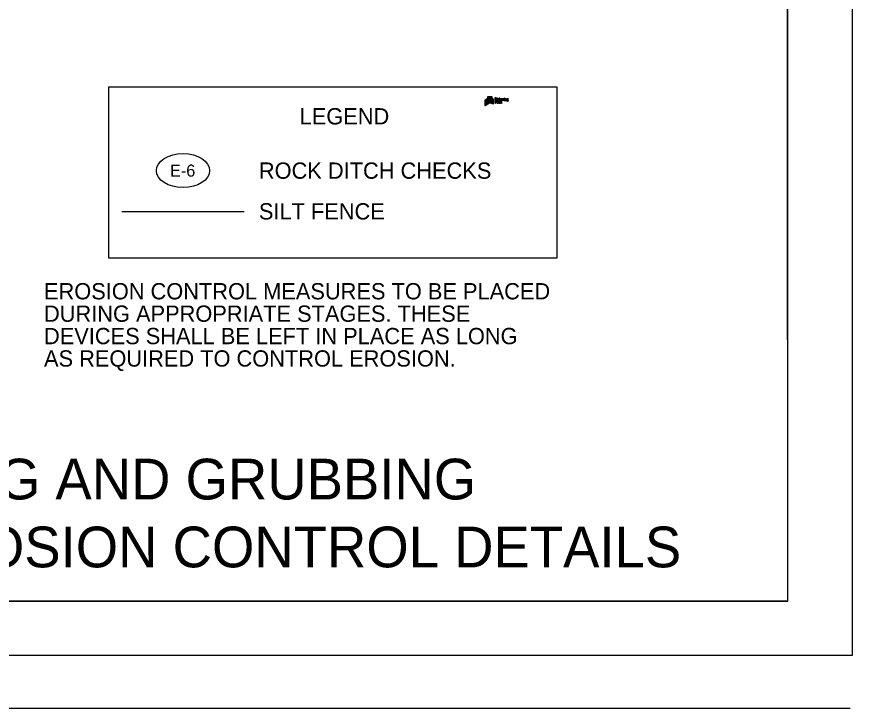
# Model space of a CAD drawing. Extents: x 7675 to 14104, y 9961 to 11168.
# Drawn here: x 9527.7 to 9835.3, y 9960.6 to 10215.3 of the extents above; entities that cross this region are included whole.
import ezdxf

# ---------------------------------------------------------------- set-up
doc = ezdxf.new("R2010")
doc.units = 0
for name, color, linetype in [('GREEN_TXT', 7, 'Continuous'), ('Legend', 7, 'Continuous'), ('SEAL-INFO', 7, 'Continuous'), ('Stage 1 Ditch Checks', 7, 'Continuous'), ('Stage 2 Flow Arrows', 7, 'Continuous')]:
    doc.layers.add(name, color=color, linetype=linetype)

msp = doc.modelspace()

# ---------------------------------------------------------------- linework, layer by layer
at = {"layer": 'GREEN_TXT'}
for p, q in [((9811.58, 10000), (9811.58, 11027.3)), ((9811.58, 10000), (8230.68, 10000)), ((8074.58, 9960.6), (9834.58, 9960.6))]:
    msp.add_line(p, q, dxfattribs=at)
at = {"layer": 'Legend'}
for p, q in [((9700.15, 10183.63), (9701.35, 10184.33)), ((9700.15, 10183.1), (9701.56, 10183.92)), ((9700.15, 10182.58), (9701.76, 10183.5)), ((9701.43, 10185.41), (9702.36, 10185.41)), ((9702.39, 10185.39), (9702.48, 10184.8)), ((9703.7, 10184.29), (9703.7, 10184.3)), ((9703.7, 10183.49), (9703.7, 10183.49)), ((9703.71, 10185.3), (9703.71, 10185.3)), ((9703.71, 10184.49), (9703.71, 10184.49)), ((9703.72, 10183.51), (9703.72, 10183.51)), ((9703.72, 10183.46), (9703.91, 10183.46)), ((9703.73, 10184.51), (9703.73, 10184.51)), ((9703.73, 10184.25), (9703.73, 10183.53)), ((9703.74, 10184.47), (9703.92, 10184.47)), ((9703.75, 10185.26), (9703.75, 10184.54)), ((9703.9, 10183.97), (9703.9, 10184.19)), ((9703.9, 10183.53), (9703.9, 10183.85)), ((9703.91, 10184.92), (9703.91, 10185.21)), ((9703.91, 10184.54), (9703.91, 10184.77)), ((9703.91, 10183.5), (9703.91, 10183.51)), ((9703.92, 10184.8), (9704.17, 10184.87)), ((9703.92, 10184.21), (9704.32, 10184.21)), ((9704.2, 10183.95), (9703.92, 10183.95)), ((9703.92, 10183.87), (9704.2, 10183.87)), ((9703.93, 10185.24), (9704.02, 10185.24)), ((9703.93, 10184.51), (9703.93, 10184.51)), ((9703.93, 10183.49), (9703.93, 10183.49)), ((9704.06, 10184.96), (9703.94, 10184.9)), ((9703.94, 10184.49), (9703.94, 10184.49)), ((9704.23, 10183.84), (9704.23, 10183.83)), ((9704.35, 10184.18), (9704.35, 10184.16)), ((9704.47, 10184.49), (9704.47, 10184.49)), ((9704.48, 10183.47), (9704.69, 10183.47)), ((9704.49, 10184.47), (9704.71, 10184.47)), ((9704.49, 10184.01), (9704.49, 10184.01)), ((9704.5, 10185.02), (9704.5, 10185.01)), ((9704.64, 10184.05), (9704.5, 10184.05)), ((9704.66, 10185.06), (9704.51, 10185.06)), ((9704.51, 10183.99), (9704.51, 10183.53)), ((9704.52, 10184.99), (9704.52, 10184.54)), ((9704.67, 10183.54), (9704.67, 10184.03)), ((9704.68, 10184.54), (9704.68, 10185.04)), ((9704.69, 10183.51), (9704.69, 10183.51)), ((9704.71, 10184.51), (9704.7, 10184.52)), ((9704.86, 10183.46), (9705.07, 10183.46)), ((9704.87, 10184.01), (9704.87, 10184.01)), ((9705.03, 10184.05), (9704.88, 10184.05)), ((9704.89, 10183.99), (9704.89, 10183.53)), ((9705.05, 10183.53), (9705.05, 10183.86)), ((9705.07, 10183.51), (9705.07, 10183.51)), ((9705.25, 10184.9), (9705.32, 10184.98)), ((9705.39, 10184.47), (9705.6, 10184.47)), ((9705.39, 10184.01), (9705.39, 10184.01)), ((9705.4, 10185.28), (9705.4, 10185.28)), ((9705.55, 10185.32), (9705.41, 10185.32)), ((9705.41, 10183.99), (9705.41, 10183.53)), ((9705.42, 10185.26), (9705.42, 10184.53)), ((9705.57, 10184.86), (9705.57, 10185.3)), ((9705.57, 10184.53), (9705.57, 10184.67)), ((9705.57, 10183.54), (9705.57, 10183.86)), ((9705.58, 10184.69), (9705.65, 10184.75)), ((9705.6, 10183.51), (9705.59, 10183.51)), ((9705.76, 10184.97), (9705.61, 10184.84)), ((9705.68, 10184.74), (9705.81, 10184.53)), ((9705.75, 10185.04), (9705.77, 10185)), ((9705.77, 10183.51), (9705.77, 10183.51)), ((9705.98, 10185.07), (9705.78, 10185.07)), ((9705.79, 10184.47), (9706.05, 10184.47)), ((9705.8, 10183.86), (9705.8, 10183.54)), ((9706.02, 10184.52), (9705.81, 10184.87)), ((9705.82, 10184.9), (9705.97, 10185.03)), ((9705.96, 10183.54), (9705.96, 10183.87)), ((9705.98, 10185.03), (9705.99, 10185.03)), ((9705.98, 10183.51), (9705.98, 10183.51)), ((9706, 10185.04), (9706, 10185.05)), ((9706.18, 10184.9), (9706.18, 10184.9)), ((9706.18, 10183.87), (9706.18, 10183.53)), ((9706.19, 10184.82), (9706.54, 10184.82)), ((9706.4, 10184.87), (9706.21, 10184.87)), ((9706.34, 10183.54), (9706.34, 10183.87)), ((9706.37, 10183.51), (9706.37, 10183.51)), ((9706.55, 10184.62), (9706.55, 10184.62)), ((9706.65, 10184.47), (9706.86, 10184.47)), ((9706.81, 10185.06), (9706.66, 10185.06)), ((9706.66, 10185.02), (9706.66, 10185.01)), ((9706.67, 10184.99), (9706.67, 10184.54)), ((9706.84, 10184.54), (9706.84, 10184.87)), ((9706.86, 10184.51), (9706.86, 10184.52)), ((9707.12, 10184.47), (9707.33, 10184.47)), ((9707.28, 10185.06), (9707.13, 10185.06)), ((9707.13, 10185.02), (9707.13, 10185.01)), ((9707.14, 10184.99), (9707.14, 10184.54)), ((9707.3, 10184.54), (9707.3, 10185.03)), ((9707.33, 10184.51), (9707.33, 10184.52)), ((9707.44, 10185.02), (9707.45, 10185.01)), ((9707.44, 10184.47), (9707.65, 10184.47)), ((9707.6, 10185.06), (9707.45, 10185.06)), ((9707.46, 10184.99), (9707.46, 10184.54)), ((9707.62, 10184.54), (9707.62, 10184.87)), ((9707.65, 10184.51), (9707.65, 10184.52)), ((9707.82, 10184.47), (9708.03, 10184.47)), ((9707.85, 10184.87), (9707.85, 10184.54)), ((9708.01, 10184.54), (9708.01, 10184.87)), ((9708.03, 10184.51), (9708.03, 10184.52)), ((9708.71, 10185.06), (9708.47, 10185.06)), ((9708.54, 10184.94), (9708.54, 10184.65)), ((9708.56, 10184.46), (9708.56, 10184.46)), ((9708.67, 10184.63), (9708.67, 10184.98)), ((9708.68, 10185), (9708.72, 10185.02)), ((9566.44, 10143.59), (9611.44, 10143.59))]:
    msp.add_line(p, q, dxfattribs=at)
msp.add_lwpolyline([(9561.57, 10189.39), (9726.57, 10189.39), (9726.57, 10126.39), (9561.57, 10126.39)], close=True, dxfattribs=at)
for points in [[(9702.82, 10185.07), (9702.7, 10185.76), (9702.67, 10185.78), (9701.11, 10185.78), (9701.08, 10185.76), (9700.96, 10185.05), (9700.12, 10184.57), (9700.11, 10184.54), (9700.11, 10184.17), (9700.14, 10184.15)], [(9701.19, 10184.66), (9700.12, 10184.04), (9700.11, 10184.02), (9700.11, 10183.65), (9700.15, 10183.63)], [(9701.39, 10184.26), (9700.12, 10183.52), (9700.11, 10183.5), (9700.11, 10183.12), (9700.15, 10183.1)], [(9701.59, 10183.86), (9700.13, 10182.99), (9700.11, 10182.97), (9700.11, 10182.6), (9700.15, 10182.58)], [(9700.14, 10184.15), (9701.28, 10184.78), (9701.3, 10184.8), (9701.41, 10185.39)], [(9703.2, 10184.59), (9703.23, 10184.61), (9703.23, 10184.93), (9703.2, 10184.96)], [(9703.2, 10184.14), (9703.23, 10184.17), (9703.23, 10184.49), (9703.2, 10184.51)], [(9703.2, 10183.69), (9703.23, 10183.71), (9703.23, 10184.04), (9703.2, 10184.06)], [(9703.2, 10183.23), (9703.23, 10183.25), (9703.23, 10183.59), (9703.2, 10183.62)], [(9704.36, 10184.32), (9703.72, 10184.32), (9703.72, 10184.32)], [(9704.11, 10185.33), (9703.74, 10185.33), (9703.74, 10185.32)], [(9704.25, 10184.01), (9704.25, 10184.01), (9704.25, 10184.01), (9704.24, 10184), (9704.23, 10183.98)], [(9704.25, 10183.82), (9704.25, 10183.82), (9704.25, 10183.82)], [(9704.26, 10183.83), (9704.27, 10183.83), (9704.27, 10184), (9704.26, 10184)], [(9704.38, 10184.16), (9704.38, 10184.16), (9704.38, 10184.3)], [(9704.46, 10183.49), (9704.46, 10183.49), (9704.46, 10183.49)], [(9704.48, 10184.03), (9704.48, 10184.03), (9704.48, 10184.03)], [(9704.49, 10183.51), (9704.48, 10183.51), (9704.48, 10183.51)], [(9704.49, 10185.04), (9704.49, 10185.04), (9704.49, 10185.04)], [(9704.5, 10184.52), (9704.5, 10184.52), (9704.49, 10184.51)], [(9704.71, 10183.49), (9704.71, 10183.49), (9704.71, 10183.49)], [(9704.73, 10184.49), (9704.73, 10184.49), (9704.73, 10184.49)], [(9704.84, 10183.49), (9704.84, 10183.49), (9704.84, 10183.49)], [(9704.86, 10184.03), (9704.86, 10184.03), (9704.86, 10184.03)], [(9704.87, 10183.51), (9704.86, 10183.51), (9704.86, 10183.51)], [(9705.1, 10183.49), (9705.1, 10183.49), (9705.1, 10183.49)], [(9705.23, 10183.98), (9705.27, 10183.95), (9705.28, 10183.96), (9705.28, 10184.08), (9705.27, 10184.1), (9705.21, 10184.1)], [(9705.26, 10184.48), (9705.29, 10184.47), (9705.31, 10184.48), (9705.31, 10184.61)], [(9705.36, 10183.49), (9705.38, 10183.47), (9705.6, 10183.47), (9705.62, 10183.49)], [(9705.57, 10184.04), (9705.55, 10184.05), (9705.4, 10184.05), (9705.38, 10184.03)], [(9705.39, 10183.51), (9705.39, 10183.51), (9705.38, 10183.51)], [(9705.4, 10184.52), (9705.39, 10184.52), (9705.39, 10184.51)], [(9705.6, 10184.51), (9705.59, 10184.52), (9705.59, 10184.52)], [(9705.75, 10183.49), (9705.77, 10183.47), (9705.98, 10183.47), (9706, 10183.49)], [(9705.8, 10184.52), (9705.8, 10184.52), (9705.79, 10184.51)], [(9706.05, 10184.51), (9706.05, 10184.52), (9706.04, 10184.52)], [(9706.14, 10183.49), (9706.16, 10183.47), (9706.37, 10183.47), (9706.39, 10183.49)], [(9706.16, 10183.51), (9706.16, 10183.51), (9706.16, 10183.51)], [(9706.52, 10184.48), (9706.55, 10184.47), (9706.57, 10184.48), (9706.57, 10184.61)], [(9706.63, 10184.49), (9706.63, 10184.49), (9706.63, 10184.49)], [(9706.64, 10185.04), (9706.64, 10185.03), (9706.64, 10185.04)], [(9706.65, 10184.52), (9706.65, 10184.52), (9706.65, 10184.51)], [(9706.88, 10184.49), (9706.88, 10184.49), (9706.88, 10184.49)], [(9707.01, 10184.99), (9707.05, 10184.95), (9707.07, 10184.97), (9707.07, 10185.09), (9707.05, 10185.1), (9707, 10185.1)], [(9707.1, 10184.49), (9707.1, 10184.49), (9707.1, 10184.49)], [(9707.11, 10185.04), (9707.11, 10185.03), (9707.11, 10185.04)], [(9707.12, 10184.52), (9707.12, 10184.52), (9707.12, 10184.51)], [(9707.35, 10184.49), (9707.35, 10184.49), (9707.35, 10184.49)], [(9707.41, 10184.49), (9707.41, 10184.49), (9707.41, 10184.49)], [(9707.43, 10185.04), (9707.43, 10185.03), (9707.43, 10185.04)], [(9707.44, 10184.52), (9707.44, 10184.52), (9707.44, 10184.51)], [(9707.67, 10184.49), (9707.67, 10184.49), (9707.67, 10184.49)], [(9707.8, 10184.49), (9707.8, 10184.49), (9707.8, 10184.49)], [(9707.83, 10184.52), (9707.82, 10184.52), (9707.82, 10184.51)], [(9708.06, 10184.49), (9708.06, 10184.49), (9708.06, 10184.49)], [(9708.24, 10184.31), (9708.24, 10184.36), (9708.23, 10184.38), (9708.18, 10184.4), (9708.09, 10184.32)]]:
    msp.add_lwpolyline(points, dxfattribs=at)
for centre, radius, start, end in [((9701.9, 10183.21), 1.62, 63.44, 116.2443), ((9701.9, 10183.21), 1.24, 63.4399, 116.2445), ((9701.9, 10183.21), 1.16, 63.4396, 116.2455), ((9701.43, 10185.39), 0.0257, 90, 169.3947), ((9701.9, 10183.21), 0.79, 63.4406, 116.2427), ((9701.9, 10183.21), 0.717, 63.443, 116.2359), ((9701.9, 10183.21), 0.326, 63.4385, 116.2484), ((9703.23, 10185.86), 2.63, 243.4196, 269.4358), ((9703.23, 10185.86), 2.24, 243.4196, 269.3512), ((9703.23, 10185.86), 2.17, 243.4196, 269.3138), ((9702.36, 10185.39), 0.0257, 9.4561, 90), ((9703.23, 10185.86), 1.79, 243.4196, 269.1919), ((9703.23, 10185.86), 1.72, 243.4196, 269.1297), ((9701.9, 10183.21), 1.69, 63.4196, 69.8726), ((9703.23, 10185.86), 1.34, 243.4196, 268.9264), ((9703.23, 10185.86), 1.27, 243.4196, 268.8202), ((9702.84, 10185.07), 0.0257, 189.9771, 243.8715), ((9703.23, 10185.86), 0.9, 243.8715, 268.4109), ((9703.72, 10184.3), 0.0212, 82.6236, 189.0072), ((9703.72, 10184.3), 0.0212, 181.5218, 256.2604), ((9703.72, 10183.48), 0.021, 103.7396, 178.4782), ((9703.72, 10183.48), 0.021, 170.9928, 274.1452), ((9703.74, 10185.3), 0.0212, 82.6236, 189.0072), ((9703.74, 10185.3), 0.0212, 181.5218, 256.2604), ((9703.73, 10184.49), 0.021, 103.7396, 178.4782), ((9703.73, 10184.49), 0.021, 170.9928, 274.1452), ((9703.71, 10184.25), 0.0259, 358.7571, 66.0872), ((9703.71, 10183.53), 0.0259, 293.9128, 6.4972), ((9703.72, 10185.26), 0.0259, 358.7571, 66.0872), ((9703.72, 10184.54), 0.0259, 293.9128, 6.4972), ((9703.92, 10184.19), 0.0234, 90, 180), ((9703.92, 10183.97), 0.0234, 180, 270), ((9703.92, 10183.85), 0.0234, 90, 180), ((9703.92, 10183.53), 0.0259, 174.5041, 246.0872), ((9703.93, 10185.21), 0.0234, 90, 180), ((9703.93, 10184.92), 0.0234, 180, 295.644), ((9703.93, 10184.77), 0.0234, 115.5876, 180), ((9703.94, 10184.54), 0.0259, 174.5041, 246.0872), ((9703.91, 10183.48), 0.021, 1.5218, 76.2604), ((9703.91, 10183.48), 0.021, 260.4108, 9.0072), ((9703.92, 10184.49), 0.021, 260.4108, 9.0071), ((9703.92, 10184.49), 0.021, 1.5218, 76.2604), ((9704.05, 10185.07), 0.163, 26.6835, 99.2796), ((9703.77, 10185.44), 0.563, 300.9494, 314.2537), ((9704.14, 10184.87), 0.455, 79.5817, 94.0737), ((9704.11, 10185.11), 0.0889, 308.8414, 26.6835), ((9703.93, 10185.45), 0.631, 293.1872, 299.0408), ((9704.2, 10183.98), 0.0351, 270, 0), ((9704.2, 10183.84), 0.0351, 0, 90), ((9704.18, 10185.12), 0.205, 346.8336, 79.1626), ((9704.15, 10185.13), 0.242, 290.3558, 346.8336), ((9704.25, 10183.83), 0.0117, 180, 270), ((9704.25, 10184), 0.0117, 0, 90), ((9704.25, 10183.83), 0.0117, 270, 0), ((9704.32, 10184.18), 0.0351, 360, 90), ((9704.36, 10184.16), 0.0117, 180, 270), ((9704.36, 10184.3), 0.0234, 360, 90), ((9704.36, 10184.16), 0.0117, 270, 0), ((9704.48, 10183.49), 0.0211, 90, 180), ((9704.48, 10183.49), 0.0211, 180, 270), ((9704.49, 10184.49), 0.0211, 90, 179.9884), ((9704.49, 10184.49), 0.0211, 180, 270), ((9704.5, 10184.03), 0.0211, 90, 180), ((9704.5, 10184.03), 0.0211, 180, 250.953), ((9704.51, 10185.04), 0.0211, 90, 180), ((9704.51, 10185.04), 0.0211, 180, 250.953), ((9704.48, 10183.99), 0.0234, 0, 70.953), ((9704.49, 10183.53), 0.0211, 270, 360), ((9704.5, 10184.99), 0.0234, 0, 70.953), ((9704.5, 10184.54), 0.0211, 270, 360), ((9704.61, 10185.23), 0.0853, 0, 180), ((9704.61, 10185.23), 0.0853, 180, 0), ((9704.64, 10184.03), 0.0234, 0, 90), ((9704.66, 10185.04), 0.0234, 0, 90), ((9704.69, 10183.54), 0.0234, 180, 270), ((9704.7, 10184.54), 0.0234, 180, 270), ((9704.69, 10183.49), 0.0211, 360, 90), ((9704.69, 10183.49), 0.0211, 270, 0), ((9704.71, 10184.49), 0.0211, 0, 90), ((9704.71, 10184.49), 0.0211, 270, 0), ((9705.11, 10184.8), 0.335, 159.4493, 258.0401), ((9705.02, 10184.86), 0.236, 89.5501, 165.3049), ((9704.86, 10183.49), 0.0211, 90, 180), ((9704.86, 10183.49), 0.0211, 180, 270), ((9704.88, 10184.03), 0.0211, 90, 180), ((9704.88, 10184.03), 0.0211, 180, 250.953), ((9704.86, 10183.99), 0.0234, 360, 70.953), ((9704.87, 10183.53), 0.0211, 270, 0), ((9705.27, 10184.8), 0.336, 157.5816, 204.7596), ((9705.1, 10184.84), 0.166, 85.3224, 146.7414), ((9705.16, 10184.8), 0.242, 216.7971, 248.1851), ((9705.02, 10184.62), 0.476, 51.4978, 89.5501), ((9705.03, 10184.03), 0.0234, 31.1414, 90), ((9705.13, 10184.87), 0.404, 257.1029, 287.6234), ((9705.06, 10184.05), 0.0117, 211.1414, 301.6677), ((9705.19, 10183.85), 0.142, 82.1433, 175.2273), ((9705.07, 10183.53), 0.0234, 180, 270), ((9705.29, 10183.66), 0.44, 100.4967, 121.6677), ((9705.14, 10184.79), 0.222, 251.3493, 311.1706), ((9705.07, 10183.49), 0.0211, 360, 90), ((9705.07, 10183.49), 0.0211, 270, 0), ((9705.1, 10184.8), 0.199, 60.5413, 85.3224), ((9705.16, 10184.92), 0.0688, 353.0776, 57.5568), ((9705.21, 10183.97), 0.0234, 33.0334, 82.1433), ((9705.24, 10184.91), 0.0117, 173.0776, 318.3482), ((9705.25, 10184.47), 0.0117, 72.7237, 107.6234), ((9705.3, 10184.61), 0.0117, 0, 131.1706), ((9705.31, 10184.98), 0.0117, 318.3482, 51.4978), ((9705.38, 10183.49), 0.0211, 90, 173.9744), ((9705.39, 10184.49), 0.0211, 90, 180), ((9705.39, 10184.49), 0.0211, 180, 270), ((9705.4, 10184.03), 0.0211, 185.1813, 250.953), ((9705.41, 10185.3), 0.0211, 90, 180), ((9705.41, 10185.3), 0.0211, 180, 250.953), ((9705.39, 10183.99), 0.0234, 360, 70.953), ((9705.39, 10183.53), 0.0211, 270, 0), ((9705.39, 10185.26), 0.0234, 360, 70.953), ((9705.4, 10184.53), 0.0187, 270, 360), ((9705.55, 10185.3), 0.0234, 360, 90), ((9705.59, 10184.86), 0.0234, 180, 311.0699), ((9705.59, 10184.67), 0.0234, 131.0699, 180), ((9705.59, 10184.53), 0.0187, 180, 270), ((9705.58, 10184.05), 0.0117, 211.1414, 301.6677), ((9705.68, 10183.87), 0.114, 354.6239, 185.3761), ((9705.59, 10183.54), 0.0234, 180, 270), ((9705.74, 10183.88), 0.221, 38.0335, 134.0608), ((9705.6, 10184.49), 0.0211, 0, 90), ((9705.6, 10184.49), 0.0211, 270, 0), ((9705.6, 10183.49), 0.0211, 6.0256, 90), ((9705.66, 10184.73), 0.0234, 31.2702, 131.0699), ((9705.78, 10185.05), 0.0234, 90, 199.4367), ((9705.77, 10183.49), 0.0211, 90, 173.9744), ((9705.74, 10184.99), 0.0234, 311.0699, 19.4367), ((9705.79, 10184.49), 0.0211, 90, 180), ((9705.79, 10184.49), 0.0211, 180, 270), ((9705.77, 10183.54), 0.0234, 270, 0), ((9705.8, 10184.53), 0.0117, 270, 31.2702), ((9705.83, 10184.88), 0.0234, 131.0699, 211.2702), ((9705.93, 10184.03), 0.0234, 218.0335, 322.8576), ((9706.12, 10183.88), 0.221, 355.8732, 142.8576), ((9706.07, 10183.88), 0.114, 354.6239, 185.3761), ((9705.98, 10183.54), 0.0234, 180, 270), ((9705.98, 10185.01), 0.0234, 90, 131.0699), ((9705.98, 10185.05), 0.0234, 0, 90), ((9705.98, 10183.49), 0.0211, 6.0256, 90), ((9705.99, 10185.04), 0.0117, 270, 0), ((9706.34, 10184.8), 0.335, 159.4493, 258.0401), ((9706.25, 10184.86), 0.236, 89.5501, 165.3049), ((9706.04, 10184.53), 0.0187, 211.2702, 270), ((9706.05, 10184.49), 0.0211, 0, 90), ((9706.05, 10184.49), 0.0211, 270, 0), ((9706.16, 10183.49), 0.0211, 90, 173.9744), ((9706.16, 10183.53), 0.0211, 270, 0), ((9706.19, 10184.79), 0.0234, 90, 181.0387), ((9706.5, 10184.8), 0.336, 181.0387, 204.7596), ((9706.5, 10184.8), 0.336, 157.5816, 162.6114), ((9706.21, 10184.89), 0.0234, 162.6114, 270), ((9706.3, 10184.89), 0.117, 0.3238, 162.4345), ((9706.39, 10184.8), 0.242, 216.7971, 248.1851), ((9706.25, 10184.62), 0.476, 70.5239, 89.5501), ((9706.37, 10184.99), 0.52, 258.6424, 285.5129), ((9706.38, 10184.85), 0.279, 253.3482, 306.5566), ((9706.37, 10183.54), 0.0234, 180, 270), ((9706.37, 10183.49), 0.0211, 6.0256, 90), ((9706.4, 10184.89), 0.0234, 270, 0.3238), ((9706.34, 10184.85), 0.226, 357.7955, 73.16), ((9706.51, 10184.47), 0.0117, 72.7237, 107.6234), ((9706.54, 10184.84), 0.0234, 270, 11.363), ((9706.56, 10184.61), 0.0117, 360, 131.1706), ((9706.65, 10184.49), 0.0211, 90, 180), ((9706.65, 10184.49), 0.0211, 180, 270), ((9706.66, 10185.04), 0.0211, 90, 180), ((9706.66, 10185.04), 0.0211, 180, 250.953), ((9706.65, 10184.54), 0.0211, 270, 0), ((9706.65, 10184.99), 0.0234, 0, 70.953), ((9706.81, 10185.03), 0.0234, 31.1414, 90), ((9706.84, 10185.05), 0.0117, 211.1414, 301.6677), ((9706.98, 10184.86), 0.142, 82.1433, 175.2273), ((9706.86, 10184.54), 0.0234, 180, 270), ((9707.08, 10184.67), 0.44, 100.4967, 121.6677), ((9706.86, 10184.49), 0.0211, 0, 90), ((9706.86, 10184.49), 0.0211, 270, 360), ((9706.99, 10184.97), 0.0234, 33.0334, 82.1433), ((9707.12, 10184.49), 0.0211, 90, 180), ((9707.12, 10184.49), 0.0211, 180, 270), ((9707.13, 10185.04), 0.0211, 90, 180), ((9707.13, 10185.04), 0.0211, 180, 250.953), ((9707.12, 10184.54), 0.0211, 270, 0), ((9707.22, 10185.23), 0.0853, 0, 180), ((9707.22, 10185.23), 0.0853, 180, 0), ((9707.12, 10184.99), 0.0234, 0, 70.953), ((9707.28, 10185.03), 0.0234, 0, 90), ((9707.33, 10184.54), 0.0234, 180, 270), ((9707.33, 10184.49), 0.0211, 0, 90), ((9707.33, 10184.49), 0.0211, 270, 0), ((9707.44, 10184.49), 0.0211, 90, 180), ((9707.44, 10184.49), 0.0211, 180, 270), ((9707.45, 10185.04), 0.0211, 90, 180), ((9707.45, 10185.04), 0.0211, 180, 250.953), ((9707.44, 10184.54), 0.0211, 270, 0), ((9707.44, 10184.99), 0.0234, 0, 70.953), ((9707.6, 10185.03), 0.0234, 31.1414, 90), ((9707.63, 10185.05), 0.0117, 211.1414, 301.6677), ((9707.74, 10184.88), 0.114, 354.6239, 185.3761), ((9707.65, 10184.54), 0.0234, 180, 270), ((9707.79, 10184.88), 0.221, 355.8732, 134.0608), ((9707.65, 10184.49), 0.0211, 0, 90), ((9707.65, 10184.49), 0.0211, 270, 0), ((9707.82, 10184.49), 0.0211, 90, 180), ((9707.82, 10184.49), 0.0211, 180, 270), ((9707.83, 10184.54), 0.0211, 270, 0), ((9708.03, 10184.54), 0.0234, 180, 270), ((9708.03, 10184.49), 0.0211, 0, 90), ((9708.03, 10184.49), 0.0211, 270, 0), ((9708.1, 10184.3), 0.0234, 131.168, 231.4342), ((9708.43, 10184.73), 0.334, 82.2082, 193.6815), ((9708.41, 10184.69), 0.516, 231.4342, 293.5615), ((9708.33, 10184.71), 0.236, 194.6951, 270.4499), ((9708.26, 10184.31), 0.0234, 180, 236.707), ((9708.37, 10184.47), 0.211, 236.707, 290.0983), ((9708.49, 10184.74), 0.225, 83.4753, 215.9717), ((9708.41, 10184.7), 0.138, 223.5865, 338.2119), ((9708.23, 10185.07), 0.606, 280.0346, 297.3499), ((9708.4, 10184.43), 0.158, 282.8124, 14.1312), ((9708.52, 10184.51), 0.0234, 13.323, 128.4784), ((9708.51, 10184.94), 0.0234, 0, 83.4753), ((9709.07, 10184.64), 0.539, 193.323, 199.0669), ((9709.07, 10184.64), 0.539, 199.0669, 199.752), ((9708.5, 10184.39), 0.213, 302.2961, 7.2223), ((9708.7, 10184.98), 0.0234, 135.4319, 180), ((9709.09, 10184.6), 0.419, 175.3173, 204.9345), ((9708.71, 10185.03), 0.0234, 315.4319, 90)]:
    msp.add_arc(centre, radius, start, end, dxfattribs=at)
msp.add_ellipse((9588.94, 10158.59), major_axis=(9.78, 0), ratio=0.638788, dxfattribs=at)
at = {"layer": 'SEAL-INFO'}
msp.add_lwpolyline([(8168.64, 11046.77), (9835.34, 11046.77), (9835.34, 9980.09), (8168.64, 9980.09)], close=True, dxfattribs=at)
at = {"layer": 'Stage 1 Ditch Checks'}
msp.add_lwpolyline([(8230.68, 10000), (9811.58, 10000), (9810.97, 10963.3), (9596.08, 10963.3), (9587.98, 10959.87), (9579.17, 10961.4), (9578.94, 10977.9), (9400.28, 10977.9), (9400.28, 11027.3), (8230.68, 11027.3)], close=True, dxfattribs=at)
msp.add_lwpolyline([(8230.68, 10000), (9811.58, 10000), (9810.97, 10963.3), (9596.08, 10963.3), (9587.98, 10959.87), (9579.17, 10961.4), (9578.94, 10977.9), (9400.28, 10977.9), (9400.28, 11027.3), (8230.68, 11027.3)], close=True, dxfattribs=at)
msp.add_lwpolyline([(8230.68, 10000), (9811.58, 10000), (9810.97, 10963.3), (9596.08, 10963.3), (9587.98, 10959.87), (9579.17, 10961.4), (9578.94, 10977.9), (9400.28, 10977.9), (9400.28, 11027.3), (8230.68, 11027.3)], close=True, dxfattribs=at)
msp.add_lwpolyline([(8230.68, 10000), (9811.58, 10000), (9810.97, 10963.3), (9596.08, 10963.3), (9587.98, 10959.87), (9579.17, 10961.4), (9578.94, 10977.9), (9400.28, 10977.9), (9400.28, 11027.3), (8230.68, 11027.3)], close=True, dxfattribs=at)
msp.add_lwpolyline([(8230.68, 10000), (9811.58, 10000), (9810.97, 10963.3), (9596.08, 10963.3), (9587.98, 10959.87), (9579.17, 10961.4), (9578.94, 10977.9), (9400.28, 10977.9), (9400.28, 11027.3), (8230.68, 11027.3)], close=True, dxfattribs=at)

# ---------------------------------------------------------------- texts
at = {"layer": 'GREEN_TXT'}
for s, p in [('CLEARING AND GRUBBING ', (9433.84, 10037.5)), ('TEMPORARY EROSION CONTROL DETAILS', (9354.41, 10012.5))]:
    msp.add_text(s, height=15, dxfattribs=at).set_placement(p)
at = {"layer": 'Legend'}
for s, height, p in [('LEGEND', 6, (9631.88, 10175.59)), ('E-6', 4.464, (9584.16, 10156.36)), ('ROCK DITCH CHECKS', 6, (9616.88, 10155.59)), ('SILT FENCE', 6, (9616.88, 10140.59))]:
    msp.add_text(s, height=height, dxfattribs=at).set_placement(p)
at = {"layer": 'Stage 2 Flow Arrows'}
for s, p in [('EROSION CONTROL MEASURES TO BE PLACED ', (9537.76, 10111.17)), ('DURING APPROPRIATE STAGES. THESE ', (9537.76, 10102.92)), ('DEVICES SHALL BE LEFT IN PLACE AS LONG ', (9537.76, 10094.67)), ('AS REQUIRED TO CONTROL EROSION.', (9537.76, 10086.42))]:
    msp.add_text(s, height=6, dxfattribs=at).set_placement(p)

doc.saveas('drawing.dxf')
